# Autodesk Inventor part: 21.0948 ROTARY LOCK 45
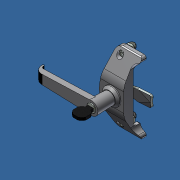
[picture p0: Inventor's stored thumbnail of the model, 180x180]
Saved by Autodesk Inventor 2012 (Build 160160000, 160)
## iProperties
Created: 2014-05
Part Number: 21.0948 ROTARY LOCK 45
Material: AL 6061-T6
Document SubType Name: Modeling
Designer: Admin
Density: 2.7 g/cm^3
Mass: 282.627 g
Surface Area: 386.231 cm^2
Volume: 104.677 cm^3
Art.-Nr.: 21.0948/0
L: -
Stück: 1
5: Drehriegelschloß
7: 21.0948/0
8: MiniTec Maschinenbau GmbH & Co KG
Author: Admin
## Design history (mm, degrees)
feature "Alias Freeform"
body "Solid1"
